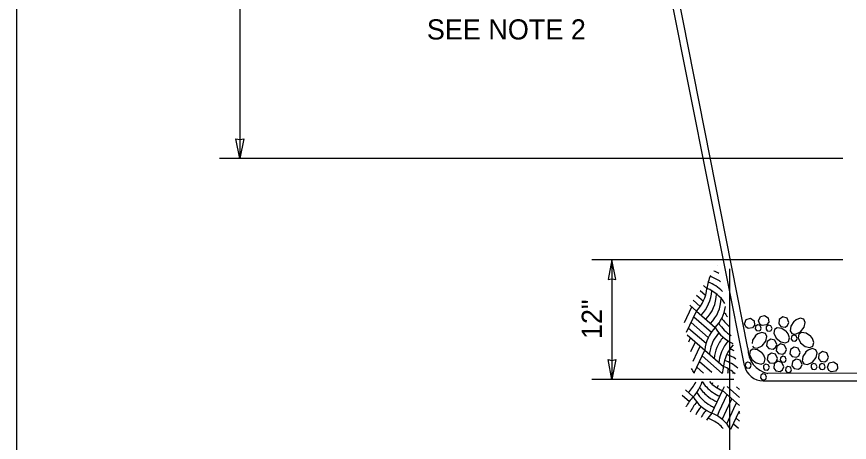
# Model space of a CAD drawing. Extents: x 99862 to 103151, y 100000 to 102076.
# Drawn here: x 99862 to 100522, y 100455 to 100793 of the extents above; entities that cross this region are included whole.
import ezdxf

# ---------------------------------------------------------------- set-up
doc = ezdxf.new("R2010")
doc.units = 0
for name, color, linetype in [('Level 1', 7, 'Continuous'), ('Level 11', 7, 'Continuous'), ('Level 14', 7, 'Continuous'), ('Level 20', 7, 'Continuous'), ('Level 4', 7, 'Continuous')]:
    doc.layers.add(name, color=color, linetype=linetype)

msp = doc.modelspace()

# ---------------------------------------------------------------- linework, layer by layer
at = {"layer": 'Level 1'}
msp.add_lwpolyline([(99862, 99999.5), (103151, 99999.5), (103151, 102075.5), (99862, 102075.5)], close=True, dxfattribs=at)
at = {"layer": 'Level 11'}
for p, q in [((100439, 100516.37), (100252.72, 101452.61)), ((100799.76, 100511.68), (100457.46, 100510.08)), ((100453.76, 100504.26), (100799.76, 100504.26))]:
    msp.add_line(p, q, dxfattribs=at)
msp.add_lwpolyline([(100441.58, 100530.18), (100257.76, 101462), (100250.38, 101463.05), (100244.4, 101508.01), (100246.9, 101532.32), (100253.69, 101536.6), (100259.06, 101534.82), (100260.48, 101526.42), (100254.77, 101515.64)], dxfattribs=at)
for centre, radius, start, end in [((100461.77, 100529.8), 20.18, 178.92299, 257.68855), ((100453.82, 100519.38), 15.12, 191.36202, 270)]:
    msp.add_arc(centre, radius, start, end, dxfattribs=at)
at = {"layer": 'Level 14'}
for p, q in [((100038.86, 101468.64), (100038.86, 100680.64)), ((100516.95, 100680.64), (100022.86, 100680.64)), ((100516.95, 100600.3), (100317.91, 100600.3)), ((100333.91, 100600.3), (100333.91, 100505.36)), ((100427.17, 100593.19), (100427.17, 100403.85)), ((100430.56, 100505.36), (100317.91, 100505.36))]:
    msp.add_line(p, q, dxfattribs=at)
at = {"layer": 'Level 4'}
for p, q in [((100406.5, 100579.91), (100409.17, 100577.58)), ((100403.75, 100576), (100408.13, 100572.18)), ((100398.25, 100568.19), (100403.87, 100563.28)), ((100401, 100572.1), (100406.32, 100567.45)), ((100391.36, 100550.45), (100397.12, 100562.87)), ((100395.5, 100564.28), (100400.85, 100559.62)), ((100393.06, 100542.82), (100400.85, 100559.62)), ((100398.76, 100555.12), (100412.73, 100542.93)), ((100400.85, 100559.62), (100415.76, 100546.59)), ((100396.68, 100550.63), (100410.28, 100538.76)), ((100393.51, 100540.79), (100407.43, 100528.63)), ((100394.6, 100546.14), (100408.47, 100534.03)), ((100394.76, 100535.18), (100396.25, 100538.4)), ((100396.45, 100527.54), (100399.98, 100535.14)), ((100398.15, 100519.9), (100401.62, 100527.39)), ((100399.11, 100510.67), (100407.43, 100528.63)), ((100401.62, 100527.39), (100403.7, 100531.88)), ((100407.43, 100528.63), (100422.35, 100515.61)), ((100405.35, 100524.14), (100421.31, 100510.2)), ((100401.19, 100515.16), (100406.58, 100510.44)), ((100403.27, 100519.65), (100413.01, 100511.14)), ((100398.96, 100510.36), (100399.11, 100510.67)), ((100399.11, 100510.67), (100399.41, 100510.4)), ((100413.32, 100501.55), (100413.98, 100502.97)), ((100417.25, 100498.73), (100418.28, 100500.95)), ((100392.13, 100497.04), (100398.27, 100491.68)), ((100413.18, 100478.65), (100421.51, 100496.62)), ((100421.51, 100496.62), (100423.02, 100499.87)), ((100421.51, 100496.62), (100435.04, 100484.8)), ((100425.12, 100499.77), (100435.04, 100491.11)), ((100432.54, 100499.6), (100435.04, 100497.42)), ((100389.57, 100492.96), (100395.24, 100488.01)), ((100418.99, 100479.89), (100425.24, 100493.36)), ((100424.8, 100481.12), (100428.97, 100490.11)), ((100392.51, 100484.09), (100392.79, 100483.84)), ((100421.37, 100473.72), (100424.8, 100481.12)), ((100424.95, 100470.14), (100430.61, 100482.36)), ((100430.61, 100482.36), (100432.69, 100486.85)), ((100417.44, 100476.54), (100418.99, 100479.89)), ((100428.23, 100465.92), (100435.04, 100480.61)), ((100432.26, 100474.61), (100435.04, 100472.18)), ((100434.34, 100479.1), (100435.04, 100478.49)), ((100430.18, 100470.12), (100434.2, 100466.61))]:
    msp.add_line(p, q, dxfattribs=at)
for points in [[(100038.86, 100680.64), (100035.78, 100696.36), (100038.86, 100695.63), (100041.95, 100696.36)], [(100333.91, 100600.3), (100330.82, 100584.57), (100333.91, 100585.3), (100336.99, 100584.57)], [(100333.91, 100505.36), (100330.82, 100521.08), (100333.91, 100520.36), (100336.99, 100521.08)]]:
    msp.add_lwpolyline(points, close=True, dxfattribs=at)
for points in [[(100438.87, 100549.53), (100440.34, 100552.97), (100443.66, 100553.87), (100446.51, 100551.95), (100446.89, 100548.48), (100445.18, 100546.31), (100441.82, 100545.85), (100439.93, 100547.03), (100438.87, 100549.53)], [(100450.1, 100551.81), (100451.57, 100555.25), (100454.89, 100556.15), (100457.74, 100554.23), (100458.12, 100550.76), (100456.42, 100548.59), (100453.05, 100548.13), (100451.17, 100549.31), (100450.11, 100551.81)], [(100474.1, 100550.63), (100472.64, 100554.08), (100469.32, 100554.98), (100466.47, 100553.06), (100466.09, 100549.59), (100467.79, 100547.42), (100471.16, 100546.96), (100473.04, 100548.14), (100474.1, 100550.63)], [(100478.07, 100551.28), (100475.68, 100547.67), (100475.22, 100543.99), (100476.49, 100541.92), (100479.44, 100541.35), (100483.32, 100543.25), (100486.2, 100546.86), (100487.07, 100550.64), (100486.01, 100553.1), (100483.02, 100553.95), (100479.95, 100552.79), (100477.94, 100551.14)], [(100452.22, 100546.04), (100451.34, 100548.1), (100449.35, 100548.65), (100447.63, 100547.49), (100447.41, 100545.41), (100448.43, 100544.11), (100450.45, 100543.83), (100451.58, 100544.54), (100452.22, 100546.04)], [(100460.82, 100545.76), (100459.94, 100547.82), (100457.95, 100548.37), (100456.24, 100547.21), (100456.01, 100545.13), (100457.03, 100543.83), (100459.06, 100543.55), (100460.18, 100544.26), (100460.82, 100545.76)], [(100445.31, 100531.86), (100446.03, 100530.68), (100448.98, 100530.12), (100452.87, 100532.02), (100455.74, 100535.62), (100456.61, 100539.4), (100455.55, 100541.87), (100452.57, 100542.71), (100449.49, 100541.55), (100447.48, 100539.9)], [(100472.08, 100543.43), (100468.47, 100545.83), (100464.79, 100546.28), (100462.72, 100545.01), (100462.15, 100542.07), (100464.05, 100538.18), (100467.66, 100535.31), (100471.44, 100534.43), (100473.9, 100535.5), (100474.75, 100538.48), (100473.59, 100541.56), (100471.94, 100543.56)], [(100480.71, 100537.92), (100479.83, 100539.99), (100477.84, 100540.53), (100476.13, 100539.37), (100475.9, 100537.29), (100476.92, 100535.99), (100478.94, 100535.71), (100480.07, 100536.42), (100480.71, 100537.92)], [(100491.33, 100539.75), (100487.73, 100542.15), (100484.04, 100542.61), (100481.98, 100541.34), (100481.41, 100538.39), (100483.31, 100534.5), (100486.91, 100531.63), (100490.7, 100530.76), (100493.16, 100531.82), (100494, 100534.81), (100492.84, 100537.88), (100491.19, 100539.89)], [(100447.62, 100540.04), (100445.22, 100536.43), (100444.91, 100533.93)], [(100464.49, 100533.1), (100463.03, 100536.54), (100459.71, 100537.45), (100456.85, 100535.52), (100456.47, 100532.06), (100458.18, 100529.89), (100461.55, 100529.42), (100463.43, 100530.61), (100464.49, 100533.1)], [(100452.74, 100526.56), (100449.13, 100528.95), (100445.45, 100529.41), (100443.39, 100528.14), (100442.82, 100525.2), (100444.72, 100521.31), (100448.32, 100518.43), (100452.1, 100517.56), (100454.56, 100518.63), (100455.41, 100521.61), (100454.25, 100524.68), (100452.6, 100526.69)], [(100472.19, 100529.17), (100470.72, 100532.61), (100467.4, 100533.52), (100464.55, 100531.59), (100464.17, 100528.13), (100465.87, 100525.96), (100469.24, 100525.49), (100471.13, 100526.68), (100472.18, 100529.17)], [(100483.02, 100526.74), (100481.55, 100530.18), (100478.23, 100531.09), (100475.38, 100529.16), (100475, 100525.69), (100476.7, 100523.53), (100480.07, 100523.06), (100481.96, 100524.24), (100483.01, 100526.74)], [(100487.54, 100527.15), (100485.15, 100523.55), (100484.69, 100519.87), (100485.96, 100517.8), (100488.91, 100517.23), (100492.79, 100519.13), (100495.67, 100522.73), (100496.54, 100526.52), (100495.48, 100528.98), (100492.49, 100529.83), (100489.42, 100528.67), (100487.41, 100527.02)], [(100505.58, 100523.1), (100504.12, 100526.54), (100500.8, 100527.45), (100497.95, 100525.52), (100497.56, 100522.06), (100499.27, 100519.89), (100502.64, 100519.43), (100504.52, 100520.61), (100505.58, 100523.1)], [(100465.04, 100521.87), (100463.57, 100525.32), (100460.25, 100526.22), (100457.4, 100524.3), (100457.02, 100520.83), (100458.73, 100518.66), (100462.09, 100518.2), (100463.98, 100519.38), (100465.04, 100521.88)], [(100472.1, 100521.19), (100471.22, 100523.25), (100469.23, 100523.79), (100467.52, 100522.64), (100467.29, 100520.56), (100468.31, 100519.26), (100470.33, 100518.98), (100471.46, 100519.69), (100472.1, 100521.18)], [(100484.61, 100517.24), (100483.14, 100520.68), (100479.82, 100521.59), (100476.97, 100519.66), (100476.58, 100516.2), (100478.29, 100514.03), (100481.66, 100513.56), (100483.54, 100514.75), (100484.6, 100517.24)], [(100444.29, 100516.59), (100443.41, 100518.65), (100441.42, 100519.2), (100439.71, 100518.04), (100439.48, 100515.96), (100440.51, 100514.66), (100442.53, 100514.38), (100443.66, 100515.09), (100444.29, 100516.59)], [(100458.71, 100515), (100457.83, 100517.06), (100455.84, 100517.61), (100454.13, 100516.45), (100453.9, 100514.37), (100454.92, 100513.07), (100456.94, 100512.79), (100458.07, 100513.5), (100458.71, 100515)], [(100470.09, 100515.43), (100468.62, 100518.87), (100465.3, 100519.77), (100462.45, 100517.85), (100462.07, 100514.38), (100463.78, 100512.21), (100467.15, 100511.75), (100469.03, 100512.93), (100470.09, 100515.43)], [(100476.22, 100513.12), (100475.34, 100515.19), (100473.34, 100515.73), (100471.63, 100514.58), (100471.4, 100512.5), (100472.43, 100511.2), (100474.45, 100510.92), (100475.58, 100511.63), (100476.22, 100513.12)], [(100496.49, 100515.4), (100495.61, 100517.46), (100493.62, 100518.01), (100491.91, 100516.85), (100491.68, 100514.77), (100492.7, 100513.47), (100494.72, 100513.19), (100495.85, 100513.9), (100496.49, 100515.4)], [(100502.93, 100515.35), (100502.05, 100517.42), (100500.06, 100517.96), (100498.35, 100516.81), (100498.12, 100514.73), (100499.15, 100513.43), (100501.17, 100513.15), (100502.3, 100513.86), (100502.93, 100515.35)], [(100504.66, 100515.07), (100506.13, 100518.51), (100509.45, 100519.41), (100512.3, 100517.49), (100512.68, 100514.02), (100510.97, 100511.86), (100507.61, 100511.39), (100505.72, 100512.57), (100504.66, 100515.07)], [(100456.37, 100507.21), (100455.49, 100509.28), (100453.5, 100509.82), (100451.79, 100508.66), (100451.56, 100506.59), (100452.58, 100505.28), (100454.6, 100505.01), (100455.73, 100505.72), (100456.37, 100507.21)]]:
    msp.add_lwpolyline(points, dxfattribs=at)
for centre, start, end in [((100439.09, 100574.62), 135.90361, 135.90451), ((100439.09, 100574.62), 135.90451, 135.90698), ((100406.28, 100567.65), 68.09551, 68.0959), ((100439.09, 100574.62), 153.82463, 174.3566), ((100402.12, 100558.67), 53.45735, 71.30215), ((100404.2, 100563.16), 61.17407, 69.83021), ((100400.04, 100554.18), 44.36094, 70.48737), ((100379.26, 100580.53), 315.90361, 354.3566), ((100382.98, 100577.28), 315.90361, 357.01126), ((100397.96, 100549.69), 32.10734, 68.09639), ((100386.71, 100574.02), 315.90361, 358.31988), ((100390.44, 100570.77), 315.90361, 357.77133), ((100394.17, 100567.51), 315.90361, 351.70028), ((100446.05, 100570.44), 213.43438, 230.92902), ((100448.13, 100574.93), 212.87781, 221.19319), ((100443.97, 100565.95), 212.24322, 238.97248), ((100437.35, 100525.67), 135.90361, 174.3566), ((100441.08, 100522.42), 138.30625, 166.2266), ((100441.89, 100561.46), 209.6434, 246.09459), ((100444.81, 100519.16), 139.1006, 157.49109), ((100448.53, 100515.91), 138.331, 147.71278), ((100441.08, 100522.42), 166.22654, 174.3566), ((100444.81, 100519.16), 157.49102, 174.3566), ((100448.53, 100515.91), 147.71269, 174.3566), ((100452.26, 100512.65), 137.94461, 174.3566), ((100417.38, 100501.19), 63.30485, 70.54646), ((100413.21, 100492.2), 47.2779, 70.48737), ((100415.29, 100496.7), 55.8662, 71.30215), ((100372.98, 100495.8), 29.6434, 37.12571), ((100392.43, 100518.56), 343.85693, 354.3566), ((100411.13, 100487.71), 47.36669, 68.09639), ((100396.16, 100515.31), 350.61464, 357.01126), ((100399.89, 100512.05), 356.2556, 358.31988), ((100372.95, 100515.85), 315.90361, 335.56989), ((100376.68, 100512.6), 315.90361, 342.78439), ((100430.64, 100520.02), 212.87781, 223.33197), ((100432.72, 100524.51), 224.01988, 248.09639), ((100426.48, 100511.04), 212.24322, 240.95992), ((100428.56, 100515.53), 213.43438, 232.94161), ((100430.64, 100520.02), 223.33188, 248.09639), ((100419.86, 100470.76), 135.90361, 154.43164), ((100423.59, 100467.5), 138.30625, 156.58561), ((100424.4, 100506.55), 209.6434, 248.09639), ((100428.56, 100515.53), 232.94154, 248.09639), ((100427.32, 100464.25), 139.1006, 154.17955), ((100431.04, 100460.99), 138.331, 147.71278), ((100426.48, 100511.04), 240.95986, 248.09639), ((100431.04, 100460.99), 147.71269, 151.77438), ((100434.77, 100457.74), 135.90361, 149.36598), ((100399.89, 100446.27), 60.95968, 70.54646), ((100401.97, 100450.76), 29.98889, 68.09634), ((100399.89, 100446.27), 42.30375, 60.95975)]:
    msp.add_arc(centre, 30.06, start, end, dxfattribs=at)

# ---------------------------------------------------------------- texts
at = {"layer": 'Level 20'}
for s, rotation, p in [(' SEE NOTE 2', 360, (100181.21, 100775.03)), ('12"', 90, (100325.91, 100537.42))]:
    msp.add_text(s, height=16, rotation=rotation, dxfattribs=at).set_placement(p)

doc.saveas('drawing.dxf')
